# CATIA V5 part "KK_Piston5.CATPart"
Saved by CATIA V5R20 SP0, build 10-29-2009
Part number: Piston5
Bounding box of the stored display mesh (mm): x -51.555 to -38.186, y -77.019 to -43.279, z 33.905 to 105
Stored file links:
  G:\Khaled_CFAO_2011\ST2M\ST2M_GR1\msallin\Khaled\Version_Finale\KK_Piston5.CATPart
  C:\Users\Mathieu\Desktop\Think Motion\JOUG-MELEE2.CATProduct
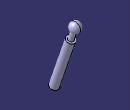
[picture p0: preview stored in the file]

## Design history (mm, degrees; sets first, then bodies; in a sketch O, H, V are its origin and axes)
External parameters (linked from other documents)
  `External.Taille du joug` = 100 mm
Set1
  Line1: linked copy from another document
  Line2: linked copy from another document
  Point1: linked copy from another document
Set2
  Plane1: type 2Lines, Element1 Line1, Element2 Line2
Body1 (main body)
  Sketch1 on Plane1, origin (-70.4493, -40.9938, 20.3771), H (0.5029, -0.8643, 0), V (0.2096, 0.122, 0.9701)
    point P1 (39.3742, 15.5054)
    line L1 (39.3742, 15.5054) -> (43.3748, 16.6697)
    line L2 (43.3748, 16.6697) -> (28.0052, 69.4786)
    line L3 (28.0052, 69.4786) -> (26.4049, 69.0128)
    line L4 (26.4049, 69.0128) -> (23.6104, 78.6144)
    arc A1 centre (20, 82.0734) radius 5 from (23.6104, 78.6144) to (18.6028, 86.8742) ccw
    point P6 (20, 82.0734)
    point P7 (18.6028, 86.8742)
    reference projected line E1 (20, 82.0734) -> (50, -21.0042) from Line2
    reference projected line E2 (20, 82.0734) -> (50, -21.0042) from Line2
    reference projected line E3 (20, 82.0734) -> (50, -21.0042) from Line2
    reference projected point E4 (20, 82.0734) from Point1
    reference projected line E5 (20, 82.0734) -> (50, -21.0042) from Line2
    distance P1 E1 = 0
    length L2 = 55 {= `External.Taille du joug` *(7/10-1/10-1/20)}
    distance E2 L2 = 4.1667 {= `External.Taille du joug` /24}
    length L4 = 10 {= `External.Taille du joug` /10}
    distance L4 E3 = 2.5 {= `External.Taille du joug` /40}
    distance P6 E4 = 0
    distance E5 P7 = 0
    radius A1 = 5 {= `External.Taille du joug` /20}
    perpendicularity: L2 L1
    parallelism: L3 L1, L4 L2
  Shaft1: profile Sketch1, axis Line2, angle 360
